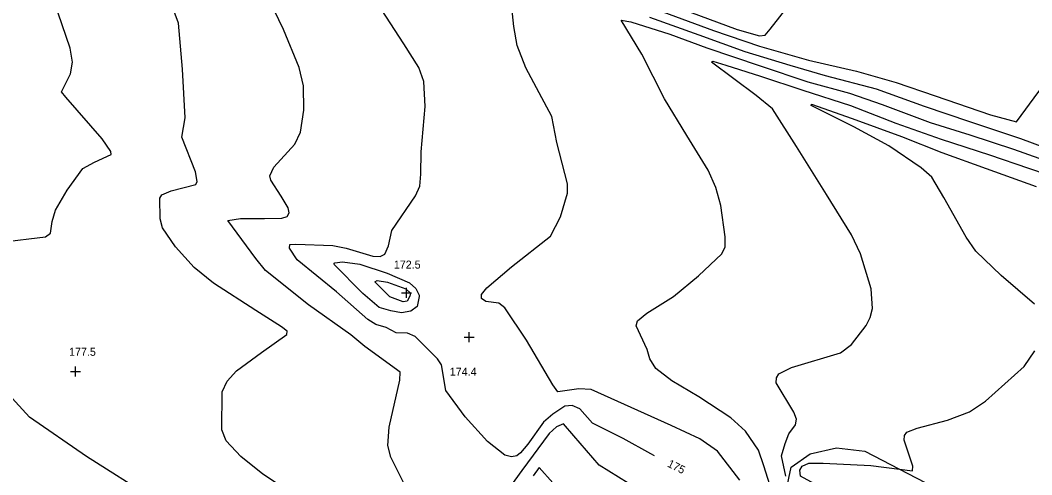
# Model space of a CAD drawing. Extents: x 1467615 to 2003689, y 770235 to 1108726.
# Drawn here: x 1995704.8 to 1995957.5, y 776657.5 to 776771.2 of the extents above; entities that cross this region are included whole.
import ezdxf

# ---------------------------------------------------------------- set-up
doc = ezdxf.new("R2010")
doc.units = 0
for name, color, linetype in [('RD_DTM_Major1', 7, 'Continuous'), ('RD_DTM_Major1_Lbl', 7, 'Continuous'), ('RD_DTM_Minor1', 7, 'Continuous'), ('RD_DTM_Minor2', 7, 'Continuous'), ('RD_DTM_Obscure', 7, 'Continuous'), ('RD_DTM_Spot_Elev', 7, 'Continuous')]:
    doc.layers.add(name, color=color, linetype=linetype)

msp = doc.modelspace()

# ---------------------------------------------------------------- linework, layer by layer
at = {"layer": 'RD_DTM_Major1'}
for points in [[(1995863.22, 776662.3), (1995862.28, 776662.77), (1995855.41, 776666.62), (1995847.72, 776670.4), (1995844.6, 776674.01), (1995842.68, 776674.88), (1995840.85, 776674.67), (1995837.87, 776672.67), (1995835.5, 776670.66), (1995831.62, 776665.21), (1995829.79, 776663), (1995828.8, 776662.3), (1995827.5, 776662.03), (1995825.84, 776662.47), (1995821.52, 776665.82), (1995815.89, 776671.98), (1995811.09, 776678.6), (1995809.99, 776684.98), (1995809, 776686.54), (1995803.45, 776692.13), (1995801.49, 776692.97), (1995798.68, 776692.99), (1995796.22, 776694.35), (1995793.6, 776695.14), (1995791.58, 776696.39), (1995783.82, 776703.29), (1995773.93, 776711.28), (1995772.02, 776714.2), (1995772.14, 776715.08), (1995773.59, 776715.21), (1995782.89, 776714.87), (1995786.19, 776714.15), (1995792.88, 776712.22), (1995794.68, 776712.14), (1995795.85, 776712.66), (1995796.8, 776714.75), (1995797.59, 776718.61), (1995803.53, 776727.29), (1995804.63, 776729.65), (1995804.85, 776732.65), (1995804.92, 776738.24), (1995805.97, 776749.56), (1995805.58, 776755.87), (1995804.36, 776759.34), (1995800.58, 776765.25), (1995795, 776773.81)], [(1995865.31, 776773.26), (1995877.96, 776768.59), (1995889.45, 776764.68), (1995901.68, 776761.22), (1995913.68, 776758.41), (1995923.62, 776755.62), (1995933.32, 776752.3), (1995947.17, 776747.55), (1995953.66, 776745.79), (1995959.27, 776753.34), (1995962.05, 776758.46), (1995962.71, 776760.08)]]:
    msp.add_lwpolyline(points, dxfattribs=at)
at = {"layer": 'RD_DTM_Minor1'}
for points in [[(1995700.03, 776715.69), (1995711.1, 776717.03), (1995712.34, 776717.96), (1995712.77, 776720.84), (1995713.6, 776723.66), (1995716.48, 776728.7), (1995720.38, 776734.14), (1995723.28, 776735.7), (1995727.5, 776737.64), (1995727.37, 776738.39), (1995725.22, 776741.48), (1995716.19, 776751.95), (1995715.11, 776753.3), (1995717.31, 776757.79), (1995717.84, 776760.69), (1995717.25, 776764.15), (1995713.27, 776775.83), (1995710.75, 776783.8), (1995710.83, 776787.66), (1995711.52, 776797.73), (1995709.69, 776802.45), (1995705.44, 776810.83), (1995702.87, 776815.06)], [(1995800.88, 776654.91), (1995797.33, 776661.97), (1995796.62, 776664.87), (1995796.94, 776669.43), (1995799.59, 776681.18), (1995799.7, 776683.22), (1995790.89, 776689.6), (1995787.35, 776692.54), (1995776.77, 776700.02), (1995766.04, 776708.56), (1995763.6, 776711.64), (1995756.6, 776721.11), (1995759.77, 776721.56), (1995765.77, 776721.6), (1995770.1, 776721.67), (1995771.46, 776722.13), (1995771.96, 776723.03), (1995771.72, 776724.27), (1995769.98, 776727.19), (1995767.37, 776731.15), (1995767.13, 776732.3), (1995768.11, 776734.41), (1995773.39, 776740.17), (1995774.78, 776743.22), (1995775.65, 776748.67), (1995775.56, 776754.79), (1995774.47, 776759.35), (1995770.56, 776768.86), (1995765.9, 776778.61)], [(1995869.75, 776774.12), (1995883.91, 776768.84), (1995889.48, 776767.24), (1995890.89, 776767.42), (1995892.13, 776768.89), (1995898.44, 776777.06)], [(1995771.42, 776653.69), (1995765.34, 776657.65), (1995759.87, 776662.13), (1995756.23, 776666.06), (1995755.13, 776668.76), (1995755.21, 776678.3), (1995756.48, 776680.92), (1995758.83, 776683.5), (1995765.03, 776688.08), (1995771.41, 776692.63), (1995771.43, 776693.45), (1995770.08, 776694.56), (1995763.62, 776698.59), (1995753.05, 776705.44), (1995748.23, 776709.35), (1995743.58, 776714.49), (1995740.35, 776719.24), (1995739.71, 776721.49), (1995739.63, 776726.65), (1995740.15, 776727.5), (1995742.46, 776728.54), (1995748.63, 776730.1), (1995748.99, 776730.86), (1995748.52, 776733.26), (1995745.13, 776741.9), (1995745.94, 776746.8), (1995745.27, 776758.91), (1995744.29, 776770.42), (1995742.07, 776776.62)], [(1995884.56, 776656.22), (1995878.98, 776663.46), (1995874.58, 776666.51), (1995867.44, 776669.89), (1995857.37, 776674.32), (1995847.39, 776678.83), (1995844.36, 776679), (1995839.1, 776678.28), (1995837.85, 776680.04), (1995831.23, 776691.18), (1995825.86, 776699.26), (1995824.38, 776700.41), (1995821.11, 776700.82), (1995820.04, 776701.61), (1995820.03, 776702.57), (1995821.37, 776704.24), (1995827.52, 776709.48), (1995837.24, 776717.19), (1995839.76, 776722.03), (1995841.5, 776727.96), (1995841.47, 776730.24), (1995838.86, 776740.59), (1995837.58, 776747.08), (1995834.42, 776752.98), (1995831.07, 776759.23), (1995828.95, 776764.87), (1995828.08, 776769.57), (1995827.61, 776774.36)], [(1995892.03, 776655.02), (1995890.57, 776659.8), (1995889.25, 776663.67), (1995885.94, 776668.43), (1995882.29, 776671.73), (1995874.28, 776676.99), (1995867.6, 776681.05), (1995863.57, 776684.11), (1995862.06, 776686.52), (1995861.38, 776688.88), (1995858.64, 776694.81), (1995859.01, 776696.01), (1995861.3, 776697.95), (1995867.97, 776702.1), (1995874.24, 776707.24), (1995880.07, 776712.76), (1995880.85, 776714.49), (1995880.9, 776717), (1995879.77, 776724.82), (1995878.55, 776729.39), (1995876.67, 776733.7), (1995871.34, 776742.35), (1995865.75, 776751.55), (1995860.06, 776762.67), (1995854.88, 776771.14), (1995857.31, 776770.78), (1995867.04, 776767.72), (1995876.31, 776764.26), (1995889.63, 776759.73), (1995901.56, 776755.79), (1995911.95, 776752.91), (1995920.1, 776750.09), (1995932.13, 776745.59), (1995941.99, 776742.5), (1995952.93, 776738.94), (1995966.73, 776734.01)], [(1995862, 776771.9), (1995874.3, 776767.49), (1995885.78, 776763.35), (1995897.01, 776759.89), (1995905.86, 776757.38), (1995918.64, 776753.99), (1995930.63, 776749.66), (1995941.93, 776745.84), (1995954.67, 776741.64), (1995964.09, 776738.13), (1995977.11, 776733.15), (1995985.13, 776729.71), (1995996.49, 776725.1), (1995996.71, 776725.42), (1995997.28, 776730.89), (1995998.44, 776744.33), (1995999.38, 776748.99), (1996003.14, 776761.34), (1996004.25, 776767.41), (1996004.08, 776771.75)], [(1995896.02, 776657.19), (1995894.98, 776662.24), (1995895.88, 776665.38), (1995896.77, 776667.81), (1995898.46, 776669.99), (1995898.74, 776671.47), (1995898.01, 776673.22), (1995893.67, 776680.53), (1995893.7, 776681.77), (1995894.34, 776682.78), (1995897.44, 776684.37), (1995909.68, 776688), (1995912.43, 776690.13), (1995916.13, 776694.85), (1995917.12, 776696.88), (1995917.7, 776699.12), (1995917.34, 776704.06), (1995914.73, 776712.75), (1995912.44, 776717.52), (1995906.21, 776727.57), (1995898.68, 776739.62), (1995892.69, 776749.05), (1995888.61, 776752.37), (1995877.5, 776760.72), (1995877.78, 776760.9), (1995881.09, 776759.96), (1995889.74, 776757.2), (1995900.28, 776753.64), (1995912.22, 776749.86), (1995923.52, 776745.47), (1995934.86, 776741.42), (1995946.91, 776737.51), (1995956.65, 776734.16), (1995970.95, 776729.33)], [(1995958.16, 776700.15), (1995949.85, 776707.38), (1995943.55, 776713.44), (1995941.07, 776716.9), (1995935.54, 776726.89), (1995932.52, 776731.96), (1995929.88, 776734.28), (1995921.77, 776739.77), (1995913.02, 776744.5), (1995902.38, 776749.83), (1995902.46, 776750.19), (1995912.63, 776746.58), (1995924.91, 776742.07), (1995935.01, 776738.11), (1995946.14, 776734.06), (1995958.63, 776729.59)], [(1995804.42, 776702.12), (1995803.95, 776699.61), (1995802.38, 776698.4), (1995799.99, 776697.99), (1995797.33, 776698.51), (1995794.45, 776699.34), (1995790.37, 776702.87), (1995783.11, 776710.15), (1995783.36, 776710.52), (1995785.26, 776710.76), (1995789.65, 776710.19), (1995796.42, 776707.93), (1995802.06, 776705.51), (1995803.57, 776704.12), (1995804.44, 776702.44), (1995804.42, 776702.12)], [(1995802.09, 776702.22), (1995801.46, 776700.92), (1995800.45, 776700.78), (1995797.09, 776702), (1995793.34, 776705.74), (1995793.95, 776706.1), (1995796.5, 776705.7), (1995801.13, 776704.02), (1995802.27, 776702.95), (1995802.09, 776702.22)], [(1995924.42, 776658.94), (1995927.73, 776658.53), (1995927.81, 776659.71), (1995925.64, 776666.19), (1995925.73, 776667.34), (1995926.27, 776668.15), (1995928.88, 776669.17), (1995936.43, 776671.17), (1995941.95, 776673.3), (1995945.96, 776675.9), (1995955.62, 776684.57), (1995958.26, 776688.54)], [(1995737.91, 776651.63), (1995721.3, 776662.1), (1995707.05, 776671.95), (1995699.17, 776680.52)], [(1995859.07, 776653.91), (1995849.41, 776659.93), (1995843.08, 776667.31), (1995840.53, 776670.28), (1995838.76, 776669.55), (1995836.89, 776667.88), (1995830.08, 776658.63), (1995824.39, 776650.81)], [(1995837.8, 776655.49), (1995834.4, 776659.33), (1995832.95, 776657.25)]]:
    msp.add_lwpolyline(points, dxfattribs=at)
at = {"layer": 'RD_DTM_Minor2'}
msp.add_lwpolyline([(1995948.47, 776621.64), (1995946.8, 776625.04), (1995944.53, 776630.4), (1995941.41, 776635.57), (1995939.55, 776636.98), (1995931, 776641.61), (1995925.35, 776645.23), (1995922.01, 776646.57), (1995920.4, 776646.93), (1995914.73, 776648.8), (1995913.04, 776648.87), (1995909.78, 776651.29), (1995905.92, 776653.8), (1995899.73, 776657.18), (1995899.53, 776658.65), (1995900.15, 776659.68), (1995901.77, 776660.48), (1995905.35, 776660.43), (1995917.25, 776659.82), (1995924.42, 776658.94)], dxfattribs=at)
at = {"layer": 'RD_DTM_Obscure'}
msp.add_lwpolyline([(1995814.05, 776480.15), (1995832.54, 776506.32), (1995870.96, 776514.65), (1995884.64, 776518.99), (1995889.04, 776524.43), (1995916.73, 776587.7), (1995916.52, 776595.92), (1995912.31, 776609.35), (1995906.06, 776627.39), (1995897.73, 776648.19), (1995896.2, 776653.97), (1995897.37, 776659.46), (1995902.1, 776662.8), (1995908.68, 776664.25), (1995915.8, 776663.41), (1995956.71, 776642.17), (1995960.59, 776638.59)], dxfattribs=at)
at = {"layer": 'RD_DTM_Spot_Elev'}
for p, q in [((1995801.25, 776701.78), (1995801.25, 776704.28)), ((1995800, 776703.03), (1995802.5, 776703.03)), ((1995815.64, 776691.91), (1995818.14, 776691.91)), ((1995816.89, 776690.66), (1995816.89, 776693.16)), ((1995718.57, 776682.14), (1995718.57, 776684.64)), ((1995717.32, 776683.39), (1995719.82, 776683.39))]:
    msp.add_line(p, q, dxfattribs=at)

# ---------------------------------------------------------------- texts
at = {"layer": 'RD_DTM_Major1_Lbl'}
msp.add_text('175', height=2, rotation=333.5044, dxfattribs=at).set_placement((1995866.28, 776659.66))
at = {"layer": 'RD_DTM_Spot_Elev'}
for s, p in [('172.5', (1995798.11, 776709.08)), ('177.5', (1995716.96, 776687.28)), ('174.4', (1995812.09, 776682.31))]:
    msp.add_text(s, height=2, dxfattribs=at).set_placement(p)

doc.saveas('drawing.dxf')
